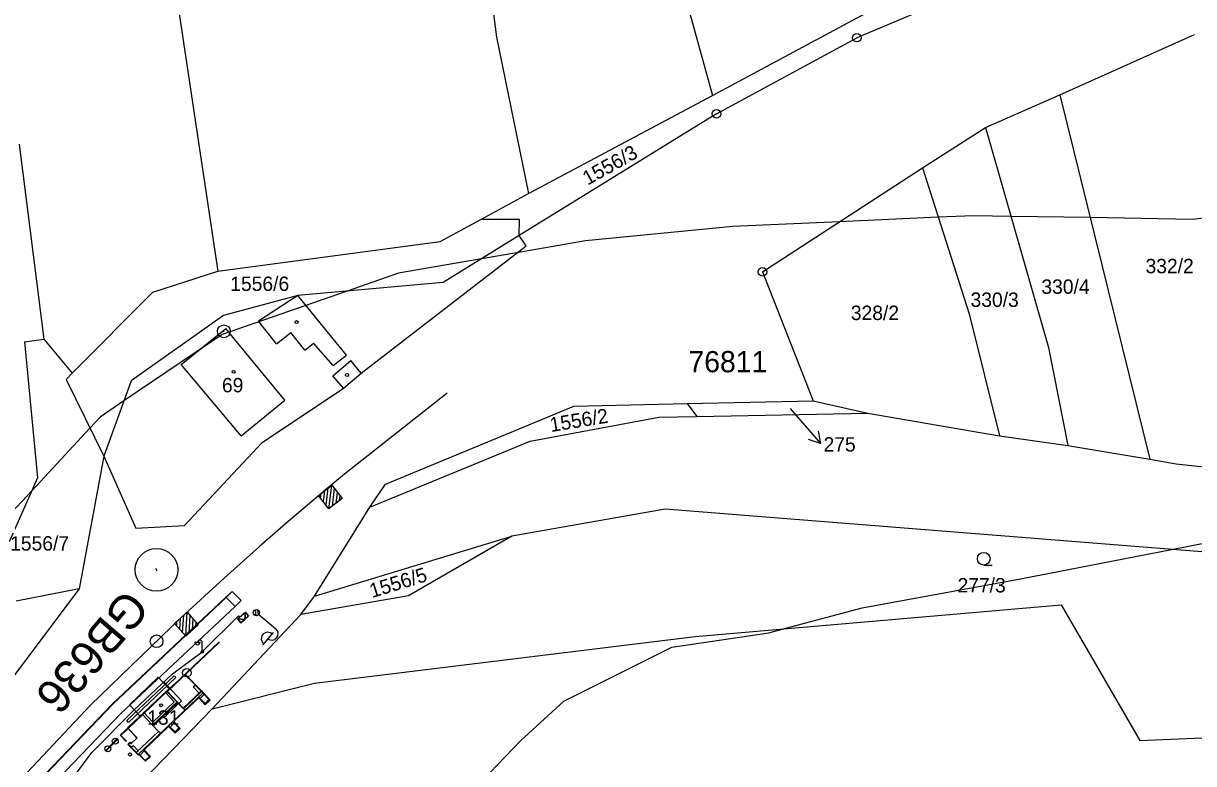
# Model space of a CAD drawing. Extents: x -756640 to -756220, y -1116060 to -1115741.
# Drawn here: x -756499.3 to -756361.1, y -1115907.5 to -1115820.2 of the extents above; entities that cross this region are included whole.
import ezdxf

# ---------------------------------------------------------------- set-up
doc = ezdxf.new("R2010")
doc.units = 0
for name, color, linetype in [('BPEJ', 7, 'Continuous'), ('GD_Demolice', 7, 'Continuous'), ('GD_Nový stav', 7, 'Continuous'), ('GD_Starý stav', 7, 'Continuous'), ('Katastr_HRANICE DRÁHY', 7, 'Continuous'), ('Katastr_Hranice parcel', 7, 'Continuous'), ('Katastr_Parcelní čísla', 7, 'Continuous'), ('Katastr_Slučkované čáry', 7, 'Continuous'), ('Katastr_Značky kultur', 7, 'Continuous'), ('Vrstva 7', 7, 'Continuous'), ('ŽBP', 7, 'Continuous')]:
    doc.layers.add(name, color=color, linetype=linetype)

msp = doc.modelspace()

# ---------------------------------------------------------------- linework, layer by layer
at = {"layer": 'BPEJ'}
for points in [[(-756355.89, -1115842.66), (-756361.22, -1115843.31), (-756373.35, -1115843.11), (-756382.69, -1115842.96), (-756387.1, -1115842.89), (-756391.28, -1115843.07), (-756402.93, -1115843.59), (-756415.53, -1115844.16), (-756432.93, -1115845.86), (-756441.01, -1115847.26), (-756445.2, -1115847.98), (-756454.99, -1115849.67), (-756461.04, -1115851.77), (-756475.79, -1115856.89), (-756487.39, -1115864.74), (-756490.21, -1115866.65), (-756491.4, -1115867.93), (-756498.24, -1115875.3), (-756501.24, -1115878.53)], [(-756444.19, -1115908.63), (-756440.57, -1115904.84), (-756435.47, -1115900.17), (-756422.74, -1115893.8), (-756411.29, -1115892.11), (-756409.41, -1115891.6), (-756400.26, -1115889.14), (-756381.59, -1115885.74), (-756363.76, -1115882.25), (-756359.95, -1115881.5), (-756342.55, -1115877.68), (-756332.79, -1115876.83)]]:
    msp.add_lwpolyline(points, dxfattribs=at)
at = {"layer": 'GD_Demolice'}
for p, q in [((-756471.89, -1115889.36), (-756471.83, -1115890.08)), ((-756471.61, -1115889.36), (-756471.55, -1115890.02)), ((-756471.47, -1115889.95), (-756469.46, -1115891.64)), ((-756469.79, -1115892.04), (-756471.05, -1115893.54)), ((-756478.56, -1115899.7), (-756478.39, -1115899.86)), ((-756477.8, -1115900.42), (-756478.56, -1115899.7)), ((-756478.39, -1115899.86), (-756477.91, -1115899.35)), ((-756477.32, -1115899.91), (-756478.05, -1115899.21)), ((-756477.32, -1115899.91), (-756477.91, -1115899.35)), ((-756477.8, -1115900.42), (-756477.32, -1115899.91)), ((-756481.35, -1115903.79), (-756482.11, -1115903.06)), ((-756481.94, -1115903.23), (-756481.46, -1115902.72)), ((-756481.35, -1115903.79), (-756481.94, -1115903.23)), ((-756481.6, -1115902.58), (-756480.87, -1115903.28)), ((-756481.35, -1115903.79), (-756480.87, -1115903.28)), ((-756486.67, -1115904.98), (-756486.52, -1115905.14)), ((-756485.82, -1115904.47), (-756486.52, -1115905.14)), ((-756484.86, -1115907.19), (-756485.62, -1115906.38)), ((-756484.99, -1115906.03), (-756485.47, -1115906.54)), ((-756484.86, -1115907.19), (-756485.47, -1115906.54)), ((-756485.11, -1115905.9), (-756484.38, -1115906.68)), ((-756484.86, -1115907.19), (-756484.38, -1115906.68))]:
    msp.add_line(p, q, dxfattribs=at)
for points in [[(-756482.33, -1115898.93), (-756480.22, -1115897.04), (-756478.24, -1115898.95)], [(-756486.96, -1115903.31), (-756482.33, -1115898.93), (-756480.41, -1115901)], [(-756480.41, -1115901), (-756478.24, -1115898.95), (-756478.02, -1115899.18), (-756485.7, -1115906.45), (-756486.91, -1115905.2), (-756486.67, -1115904.98)], [(-756482.33, -1115898.93), (-756480.41, -1115901), (-756478.24, -1115898.95)], [(-756486.96, -1115903.31), (-756485.82, -1115904.47)]]:
    msp.add_lwpolyline(points, dxfattribs=at)
msp.add_circle((-756471.76, -1115889.71), 0.375, dxfattribs=at)
msp.add_circle((-756471.76, -1115889.71), 0.375, dxfattribs=at)
for centre, start, end in [((-756470.43, -1115892.78), 49.3451, 230.7502), ((-756469.94, -1115892.21), 230.0476, 50.0476)]:
    msp.add_arc(centre, 0.75, start, end, dxfattribs=at)
at = {"layer": 'GD_Nový stav'}
for p, q in [((-756473.06, -1115889.67), (-756473.12, -1115890.51)), ((-756473.12, -1115890.51), (-756473.06, -1115889.67)), ((-756472.67, -1115890.12), (-756473.06, -1115889.67)), ((-756473.12, -1115890.51), (-756473.97, -1115890.45)), ((-756473.97, -1115890.45), (-756473.58, -1115890.9)), ((-756473.97, -1115890.45), (-756473.12, -1115890.51)), ((-756473.58, -1115890.9), (-756473.12, -1115890.51)), ((-756473.12, -1115890.51), (-756472.67, -1115890.12)), ((-756478.34, -1115893.23), (-756479.07, -1115893.23)), ((-756478.01, -1115894.39), (-756478.18, -1115894.22)), ((-756478.14, -1115894.21), (-756478.14, -1115893.23)), ((-756478.07, -1115894.47), (-756478.26, -1115894.28)), ((-756481.01, -1115900.32), (-756483.92, -1115903.07)), ((-756481.01, -1115900.32), (-756481.09, -1115900.24)), ((-756480.18, -1115901.2), (-756480.39, -1115900.98)), ((-756483.92, -1115903.07), (-756484, -1115902.98)), ((-756483.09, -1115903.95), (-756483.3, -1115903.73))]:
    msp.add_line(p, q, dxfattribs=at)
for points in [[(-756473.97, -1115890.45), (-756473.06, -1115889.67), (-756472.67, -1115890.12), (-756473.58, -1115890.9)], [(-756482.26, -1115898.93), (-756476.19, -1115893.2), (-756476.15, -1115893.23), (-756482.22, -1115898.97)], [(-756487.06, -1115902.44), (-756481.46, -1115897.15), (-756481.26, -1115897.37), (-756486.86, -1115902.66)], [(-756486.73, -1115900.6), (-756483.36, -1115897.33), (-756482.07, -1115898.69), (-756485.49, -1115901.92)], [(-756478.98, -1115898.25), (-756478.28, -1115898.99), (-756478.5, -1115899.2), (-756479.2, -1115898.45)], [(-756483.99, -1115902.63), (-756481.45, -1115900.23), (-756482.51, -1115899.1), (-756482.33, -1115898.93), (-756481.09, -1115900.24), (-756484, -1115902.98), (-756485.24, -1115901.68), (-756485.05, -1115901.5)], [(-756485.24, -1115901.68), (-756484, -1115902.98), (-756481.09, -1115900.24), (-756482.33, -1115898.93)], [(-756478.07, -1115899.21), (-756477.32, -1115900.01), (-756477.83, -1115900.49), (-756478.58, -1115899.69)], [(-756481.62, -1115902.56), (-756480.87, -1115903.36), (-756481.38, -1115903.84), (-756482.13, -1115903.04)], [(-756486.48, -1115905.63), (-756485.93, -1115906.22), (-756485.71, -1115906.01), (-756486.26, -1115905.43)], [(-756485.14, -1115905.88), (-756484.38, -1115906.68), (-756484.89, -1115907.16), (-756485.65, -1115906.36)]]:
    msp.add_lwpolyline(points, close=True, dxfattribs=at)
for points in [[(-756510.49, -1115928.5), (-756494.73, -1115910.99), (-756491.19, -1115906.22), (-756486.18, -1115901.19), (-756481.67, -1115896.93), (-756478.14, -1115894.35), (-756473.87, -1115890.1), (-756473.74, -1115890.25)], [(-756476.17, -1115893.21), (-756482.24, -1115898.95)], [(-756482.55, -1115901.61), (-756482.37, -1115901.79), (-756480.59, -1115900.11), (-756482.69, -1115897.89)], [(-756484, -1115902.98), (-756481.09, -1115900.24), (-756480.39, -1115900.98), (-756478.28, -1115898.99), (-756478.07, -1115899.21), (-756485.72, -1115906.43), (-756485.93, -1115906.22), (-756483.3, -1115903.73), (-756484, -1115902.98)], [(-756485.24, -1115901.75), (-756487.82, -1115904.18), (-756487.13, -1115904.91), (-756487.1, -1115904.88), (-756487.75, -1115904.19), (-756485.2, -1115901.78), (-756485.24, -1115901.75)], [(-756487.11, -1115904.89), (-756487.78, -1115904.19), (-756485.22, -1115901.76)], [(-756488.11, -1115904.64), (-756488.18, -1115904.57), (-756489.58, -1115906), (-756489.51, -1115906.07), (-756488.11, -1115904.64)], [(-756488.11, -1115904.64), (-756488.18, -1115904.57), (-756489.58, -1115906), (-756489.51, -1115906.07), (-756488.11, -1115904.64)]]:
    msp.add_lwpolyline(points, dxfattribs=at)
for centre, radius in [((-756478.14, -1115894.35), 0.141), ((-756478.14, -1115894.35), 0.141), ((-756483, -1115900.64), 0.175), ((-756488.41, -1115904.87), 0.35), ((-756489.28, -1115905.77), 0.35), ((-756486.68, -1115906.45), 0.188)]:
    msp.add_circle(centre, radius, dxfattribs=at)
for centre, start, end in [((-756478.7, -1115893.23), 179.2811, 0.6862), ((-756478.42, -1115893.23), 359.9837, 179.9837)]:
    msp.add_arc(centre, 0.281, start, end, dxfattribs=at)
at = {"layer": 'GD_Starý stav'}
for p, q in [((-756449.25, -1115863.83), (-756461.35, -1115873.36)), ((-756461.35, -1115873.36), (-756463.65, -1115875.28)), ((-756463.19, -1115877.47), (-756462.86, -1115874.66)), ((-756463.65, -1115875.28), (-756468.32, -1115879.23)), ((-756464.18, -1115876.22), (-756464.11, -1115875.64)), ((-756463.85, -1115876.63), (-756463.69, -1115875.31)), ((-756463.52, -1115877.05), (-756463.28, -1115874.98)), ((-756462.78, -1115877.14), (-756462.53, -1115875.07)), ((-756462.36, -1115876.81), (-756462.2, -1115875.49)), ((-756461.94, -1115876.48), (-756461.88, -1115875.91)), ((-756468.32, -1115879.23), (-756471.39, -1115881.91)), ((-756471.39, -1115881.91), (-756475.58, -1115885.63)), ((-756475.58, -1115885.63), (-756480.69, -1115890.31)), ((-756474.6, -1115887.22), (-756475.45, -1115887.95)), ((-756475.33, -1115887.92), (-756474.6, -1115887.22)), ((-756475.45, -1115887.95), (-756488.75, -1115900.48)), ((-756488.72, -1115900.49), (-756475.33, -1115887.92)), ((-756475.33, -1115887.92), (-756474.28, -1115888.97)), ((-756480.46, -1115892.07), (-756480.33, -1115890)), ((-756480.1, -1115892.47), (-756479.94, -1115889.65)), ((-756479.71, -1115892.12), (-756479.59, -1115890.04)), ((-756480.69, -1115890.31), (-756491.34, -1115900.62)), ((-756481.16, -1115891.28), (-756481.13, -1115890.7)), ((-756480.81, -1115891.68), (-756480.73, -1115890.35)), ((-756479.31, -1115891.77), (-756479.23, -1115890.44)), ((-756478.91, -1115891.41), (-756478.88, -1115890.84)), ((-756491.34, -1115900.62), (-756504.48, -1115914.54)), ((-756488.75, -1115900.48), (-756500.01, -1115912.23)), ((-756499.99, -1115912.26), (-756488.72, -1115900.49))]:
    msp.add_line(p, q, dxfattribs=at)
for points in [[(-756464.43, -1115875.9), (-756462.86, -1115874.66), (-756461.62, -1115876.23), (-756463.19, -1115877.47)], [(-756481.43, -1115890.98), (-756479.94, -1115889.65), (-756478.61, -1115891.14), (-756480.1, -1115892.47)]]:
    msp.add_lwpolyline(points, close=True, dxfattribs=at)
msp.add_lwpolyline([(-756518.61, -1115933.55), (-756517.48, -1115934.49), (-756513.05, -1115929.32), (-756507.59, -1115923.05), (-756498.92, -1115913.24), (-756487.78, -1115901.64), (-756474.28, -1115888.97), (-756473.57, -1115888.27), (-756474.6, -1115887.22)], dxfattribs=at)
at = {"layer": 'Katastr_HRANICE DRÁHY'}
for points in [[(-756379.08, -1115812.68), (-756400.89, -1115821.88)], [(-756417.46, -1115830.87), (-756400.89, -1115821.88)], [(-756376.92, -1115828.62), (-756361.05, -1115821.51)], [(-756385.69, -1115832.48), (-756376.92, -1115828.62)], [(-756417.46, -1115830.87), (-756440.74, -1115845.23)], [(-756393.14, -1115837.23), (-756385.69, -1115832.48)], [(-756412.02, -1115849.5), (-756393.14, -1115837.23)], [(-756439.93, -1115846.42), (-756440.74, -1115845.23)], [(-756459.39, -1115861.44), (-756439.93, -1115846.42)], [(-756412.02, -1115849.5), (-756406.03, -1115864.73)], [(-756461.48, -1115863.23), (-756459.39, -1115861.44)], [(-756471.07, -1115869.62), (-756461.48, -1115863.23)], [(-756434.3, -1115865.34), (-756420.92, -1115865.05)], [(-756420.92, -1115865.05), (-756406.03, -1115864.73)], [(-756444.45, -1115869.55), (-756434.3, -1115865.34)], [(-756480.23, -1115879.43), (-756471.07, -1115869.62)], [(-756456.53, -1115874.56), (-756444.45, -1115869.55)], [(-756489.77, -1115871.26), (-756492.66, -1115886.9)], [(-756489.77, -1115871.26), (-756485.99, -1115879.76)], [(-756458.35, -1115877.27), (-756456.53, -1115874.56)], [(-756464.9, -1115887.76), (-756458.35, -1115877.27)], [(-756485.99, -1115879.76), (-756480.23, -1115879.43)], [(-756492.66, -1115886.9), (-756508.12, -1115907.44)], [(-756466.5, -1115889.92), (-756464.9, -1115887.76)], [(-756466.5, -1115889.92), (-756476.99, -1115901.06)], [(-756476.99, -1115901.06), (-756486.16, -1115910.54)]]:
    msp.add_lwpolyline(points, dxfattribs=at)
at = {"layer": 'Katastr_Hranice parcel'}
for points in [[(-756484.84, -1115792.54), (-756476.32, -1115849.42)], [(-756444.74, -1115811.37), (-756443.42, -1115821.82)], [(-756417.92, -1115828.69), (-756398.23, -1115818.12)], [(-756420.59, -1115819.01), (-756417.92, -1115828.69)], [(-756443.42, -1115821.82), (-756439.65, -1115840.25)], [(-756439.65, -1115840.25), (-756417.92, -1115828.69)], [(-756376.92, -1115828.62), (-756366.32, -1115871.62)], [(-756385.69, -1115832.48), (-756378.27, -1115858.42)], [(-756499.77, -1115834.45), (-756496.86, -1115857.44)], [(-756393.14, -1115837.23), (-756387.65, -1115854.44)], [(-756445.28, -1115843.31), (-756439.65, -1115840.25)], [(-756450.06, -1115845.91), (-756445.28, -1115843.31)], [(-756440.69, -1115843.31), (-756445.28, -1115843.31)], [(-756440.74, -1115845.23), (-756440.69, -1115843.31)], [(-756440.74, -1115845.23), (-756449.72, -1115850.77)], [(-756476.32, -1115849.42), (-756450.06, -1115845.91)], [(-756483.98, -1115851.89), (-756476.32, -1115849.42)], [(-756449.72, -1115850.77), (-756466.87, -1115852.29)], [(-756493.49, -1115861.47), (-756483.98, -1115851.89)], [(-756466.87, -1115852.29), (-756475.62, -1115854.64)], [(-756475.62, -1115854.64), (-756486.53, -1115862.38)], [(-756387.65, -1115854.44), (-756384.07, -1115868.86)], [(-756499.11, -1115857.77), (-756496.86, -1115857.44)], [(-756499.11, -1115857.77), (-756497.58, -1115873.81)], [(-756496.86, -1115857.44), (-756493.49, -1115861.47)], [(-756378.27, -1115858.42), (-756375.99, -1115870.01)], [(-756493.49, -1115861.47), (-756494.22, -1115862.2)], [(-756494.22, -1115862.2), (-756489.77, -1115871.26)], [(-756486.53, -1115862.38), (-756489.77, -1115871.26)], [(-756420.92, -1115865.05), (-756419.79, -1115866.57)], [(-756406.03, -1115864.73), (-756399.6, -1115866.17)], [(-756424.26, -1115866.66), (-756419.79, -1115866.57)], [(-756419.79, -1115866.57), (-756399.6, -1115866.17)], [(-756399.6, -1115866.17), (-756384.07, -1115868.86)], [(-756439.44, -1115869.47), (-756424.26, -1115866.66)], [(-756384.07, -1115868.86), (-756375.99, -1115870.01)], [(-756458.35, -1115877.27), (-756439.44, -1115869.47)], [(-756375.99, -1115870.01), (-756366.32, -1115871.62)], [(-756366.32, -1115871.62), (-756363.21, -1115872.14)], [(-756363.21, -1115872.14), (-756348.29, -1115873.78)], [(-756497.58, -1115873.81), (-756500.95, -1115881.37)], [(-756423.52, -1115877.5), (-756441.61, -1115880.7)], [(-756323.04, -1115885.48), (-756423.52, -1115877.5)], [(-756464.9, -1115887.76), (-756441.61, -1115880.7)], [(-756441.61, -1115880.7), (-756453.8, -1115887.71)], [(-756492.66, -1115886.9), (-756500.09, -1115888.35)], [(-756453.8, -1115887.71), (-756466.5, -1115889.92)], [(-756419.96, -1115892.51), (-756376.76, -1115888.79)], [(-756376.76, -1115888.79), (-756367.5, -1115904.78)], [(-756464.89, -1115898.03), (-756419.96, -1115892.51)], [(-756482.31, -1115899.02), (-756480.17, -1115896.98)], [(-756478.19, -1115898.99), (-756480.17, -1115896.98)], [(-756476.99, -1115901.06), (-756464.89, -1115898.03)], [(-756482.31, -1115899.02), (-756486.91, -1115903.37)], [(-756477.97, -1115899.22), (-756478.19, -1115898.99)], [(-756477.21, -1115900.02), (-756477.97, -1115899.22)], [(-756481.53, -1115902.57), (-756478.56, -1115899.77)], [(-756478.56, -1115899.77), (-756477.79, -1115900.58)], [(-756477.79, -1115900.58), (-756477.21, -1115900.02)], [(-756486.91, -1115903.37), (-756485.86, -1115904.54)], [(-756485.02, -1115905.88), (-756482.12, -1115903.14)], [(-756482.12, -1115903.14), (-756481.36, -1115903.94)], [(-756480.77, -1115903.38), (-756481.53, -1115902.57)], [(-756481.36, -1115903.94), (-756480.77, -1115903.38)], [(-756367.5, -1115904.78), (-756331.81, -1115903.26)], [(-756486.69, -1115905.05), (-756486.92, -1115905.26)], [(-756486.92, -1115905.26), (-756485.69, -1115906.51)], [(-756486.56, -1115905.19), (-756486.69, -1115905.05)], [(-756485.86, -1115904.54), (-756486.56, -1115905.19)], [(-756485.69, -1115906.51), (-756485.62, -1115906.44)], [(-756485.62, -1115906.44), (-756484.86, -1115907.25)], [(-756484.27, -1115906.69), (-756485.02, -1115905.88)], [(-756484.86, -1115907.25), (-756484.27, -1115906.69)]]:
    msp.add_lwpolyline(points, dxfattribs=at)
at = {"layer": 'Katastr_Parcelní čísla'}
for p, q in [((-756408.75, -1115865.64), (-756407.79, -1115866.75)), ((-756405.45, -1115868.3), (-756405.17, -1115869.77))]:
    msp.add_line(p, q, dxfattribs=at)
msp.add_lwpolyline([(-756407.79, -1115866.75), (-756405.17, -1115869.77), (-756406.58, -1115869.28)], dxfattribs=at)
at = {"layer": 'Katastr_Slučkované čáry'}
for points in [[(-756466.87, -1115852.29), (-756471.5, -1115855.31)], [(-756461.12, -1115859.32), (-756466.87, -1115852.29)], [(-756469.37, -1115857.99), (-756471.5, -1115855.31)], [(-756480.62, -1115860.45), (-756475.36, -1115856.19)], [(-756474.48, -1115857.26), (-756475.36, -1115856.19)], [(-756469.37, -1115857.99), (-756467.7, -1115856.66)], [(-756466.04, -1115858.75), (-756467.7, -1115856.66)], [(-756468.39, -1115864.63), (-756474.48, -1115857.26)], [(-756466.04, -1115858.75), (-756465.01, -1115857.93)], [(-756462.69, -1115860.54), (-756465.01, -1115857.93)], [(-756462.69, -1115860.54), (-756461.12, -1115859.32)], [(-756473.55, -1115868.86), (-756480.62, -1115860.45)], [(-756462.73, -1115861.77), (-756460.61, -1115859.95)], [(-756459.39, -1115861.44), (-756460.61, -1115859.95)], [(-756461.48, -1115863.23), (-756462.73, -1115861.77)], [(-756473.55, -1115868.86), (-756468.39, -1115864.63)], [(-756480.35, -1115901.06), (-756482.31, -1115899.02)], [(-756478.19, -1115898.99), (-756480.35, -1115901.06)]]:
    msp.add_lwpolyline(points, dxfattribs=at)
at = {"layer": 'Katastr_Značky kultur'}
for p, q in [((-756400.94, -1115821.88), (-756400.84, -1115821.88)), ((-756417.51, -1115830.87), (-756417.41, -1115830.87)), ((-756412.07, -1115849.5), (-756411.97, -1115849.5)), ((-756475.65, -1115856.52), (-756475.55, -1115856.52)), ((-756385.91, -1115884.11), (-756384.91, -1115884.11))]:
    msp.add_line(p, q, dxfattribs=at)
for centre, radius in [((-756400.89, -1115821.88), 0.499), ((-756417.46, -1115830.87), 0.499), ((-756412.02, -1115849.5), 0.499), ((-756467.01, -1115855.43), 0.175), ((-756475.6, -1115856.52), 0.756), ((-756474.45, -1115861.3), 0.175), ((-756461.06, -1115861.68), 0.175), ((-756385.91, -1115883.36), 0.75)]:
    msp.add_circle(centre, radius, dxfattribs=at)
at = {"layer": 'Vrstva 7'}
msp.add_line((-756479.93, -1115896.77), (-756480, -1115896.83), dxfattribs=at)
for centre, radius in [((-756483.54, -1115893.08), 0.75), ((-756479.96, -1115896.8), 0.5)]:
    msp.add_circle(centre, radius, dxfattribs=at)
at = {"layer": 'ŽBP'}
msp.add_line((-756483.47, -1115884.81), (-756483.62, -1115884.51), dxfattribs=at)
msp.add_circle((-756483.54, -1115884.66), 2.52, dxfattribs=at)

# ---------------------------------------------------------------- texts
at = {"layer": 'BPEJ'}
msp.add_text('76811', height=2.5, dxfattribs=at).set_placement((-756420.76, -1115861.35))
at = {"layer": 'Katastr_Parcelní čísla'}
for s, rotation, p in [('1556/3', 29.2299, (-756432.66, -1115839.34)), ('1556/2', 9.3485, (-756436.99, -1115868.41)), ('1556/5', 17.1589, (-756458.1, -1115888))]:
    msp.add_text(s, height=1.7, rotation=rotation, dxfattribs=at).set_placement(p)
for s, p in [('332/2', (-756366.82, -1115849.67)), ('1556/6', (-756474.84, -1115851.76)), ('330/4', (-756379.11, -1115852.1)), ('330/3', (-756387.47, -1115853.64)), ('328/2', (-756401.6, -1115855.19)), ('69', (-756475.82, -1115863.72)), ('275', (-756404.82, -1115870.71)), ('1556/7', (-756500.82, -1115882.39)), ('277/3', (-756389.01, -1115887.33)), ('131', (-756484.64, -1115902.94))]:
    msp.add_text(s, height=1.7, dxfattribs=at).set_placement(p)
at = {"layer": 'ŽBP'}
msp.add_text('GB636', height=4, rotation=229.3442, dxfattribs=at).set_placement((-756487.2, -1115886.72))

doc.saveas('drawing.dxf')
